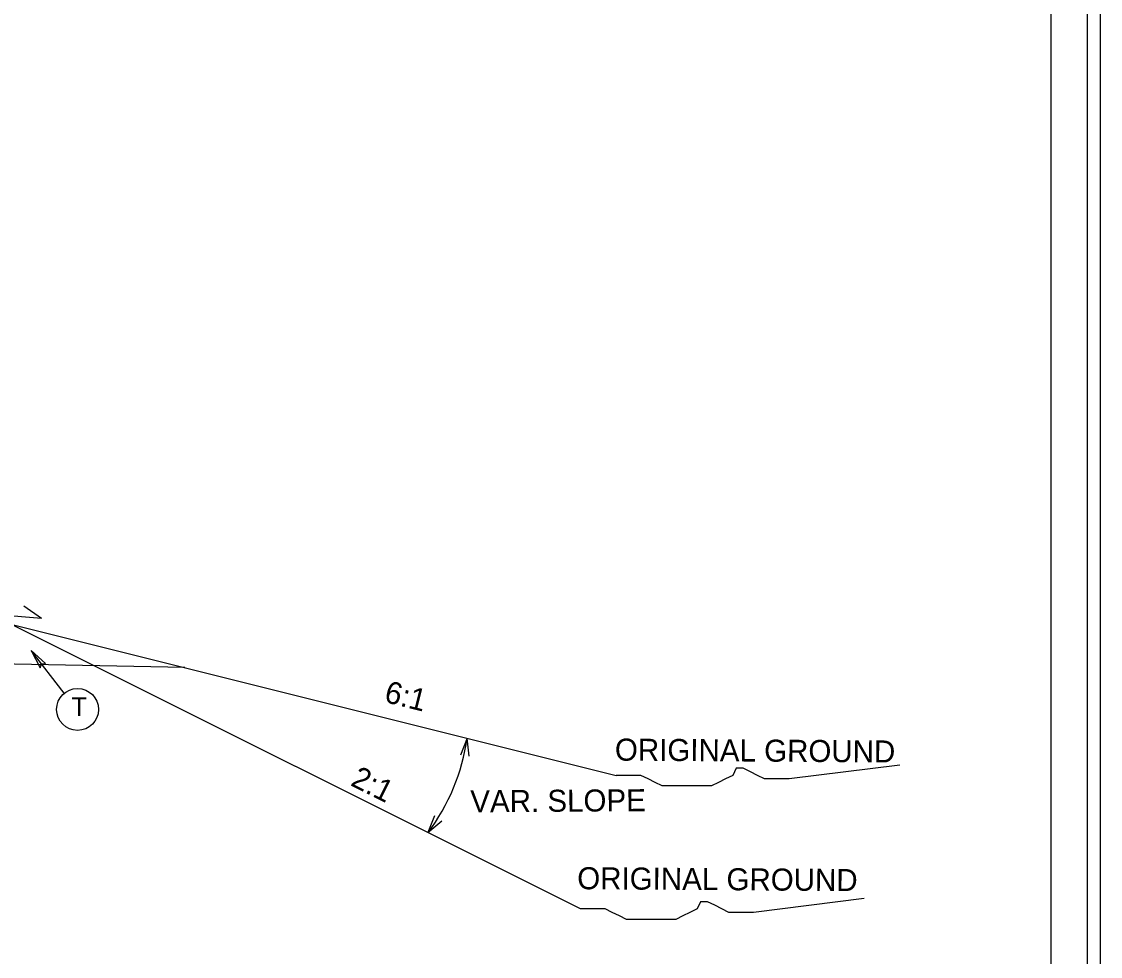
# Model space of a CAD drawing. Extents: x 2111095 to 2115970, y 670428 to 672393.
# Drawn here: x 2112895.7 to 2113267.5, y 671662.9 to 671985.2 of the extents above; entities that cross this region are included whole.
import ezdxf

# ---------------------------------------------------------------- set-up
doc = ezdxf.new("R2010")
doc.units = 0
for name, color, linetype in [('Old_Level_1', 7, 'Continuous'), ('Old_Level_11', 7, 'Continuous'), ('Old_Level_20', 7, 'Continuous'), ('Sheet Plot Border Inside CELL', 7, 'Continuous'), ('Sheet Plot Border Outside CELL', 7, 'Continuous'), ('Sheet Typical CELL', 7, 'Continuous'), ('Typical Pavement Slope CELL', 7, 'Continuous'), ('Typical Pavement Slope Information CELL', 7, 'Continuous')]:
    doc.layers.add(name, color=color, linetype=linetype)

msp = doc.modelspace()

# ---------------------------------------------------------------- linework, layer by layer
at = {"layer": 'Old_Level_1'}
for p, q in [((2112891.98, 671777.43), (2113100.62, 671725.29)), ((2113088.33, 671679.28), (2112891.98, 671777.43))]:
    msp.add_line(p, q, dxfattribs=at)
for points in [[(2113198.38, 671728.84), (2113160.25, 671724.08), (2113157.82, 671724.08), (2113154.16, 671724.08), (2113151.73, 671724.08), (2113149.3, 671725.3), (2113146.86, 671726.52), (2113144.43, 671727.74), (2113142, 671727.74), (2113140.78, 671725.3), (2113138.34, 671724.08), (2113135.91, 671722.86), (2113133.48, 671721.65), (2113131.04, 671721.65), (2113128.61, 671721.65), (2113126.18, 671721.65), (2113123.74, 671721.65), (2113121.31, 671721.65), (2113118.88, 671721.65), (2113116.44, 671721.65), (2113114.01, 671722.86), (2113111.58, 671724.08), (2113109.14, 671725.29), (2113105.49, 671725.29), (2113103.06, 671725.29), (2113100.62, 671725.29)], [(2113186.08, 671682.82), (2113147.96, 671678.07), (2113145.52, 671678.07), (2113141.87, 671678.07), (2113139.44, 671678.07), (2113137, 671679.28), (2113134.57, 671680.5), (2113132.14, 671681.72), (2113129.7, 671681.72), (2113128.48, 671679.28), (2113126.05, 671678.07), (2113123.62, 671676.85), (2113121.18, 671675.63), (2113118.75, 671675.63), (2113116.32, 671675.63), (2113113.88, 671675.63), (2113111.45, 671675.63), (2113109.02, 671675.63), (2113106.58, 671675.63), (2113104.15, 671675.63), (2113101.72, 671676.84), (2113099.28, 671678.07), (2113096.85, 671679.28), (2113093.19, 671679.28), (2113090.76, 671679.28), (2113088.33, 671679.28)]]:
    msp.add_lwpolyline(points, dxfattribs=at)
at = {"layer": 'Old_Level_11'}
msp.add_line((2112910.39, 671753.63), (2112898.92, 671768.39), dxfattribs=at)
msp.add_lwpolyline([(2112903.93, 671763.82), (2112898.92, 671768.39), (2112902.1, 671762.35), (2112902.52, 671763.76)], close=True, dxfattribs=at)
for points in [[(2113049.96, 671731.91), (2113049.24, 671738.13), (2113046.95, 671732.3)], [(2113038.03, 671711.4), (2113035.71, 671705.58), (2113040.49, 671709.62)]]:
    msp.add_lwpolyline(points, dxfattribs=at)
msp.add_circle((2112914.95, 671748.03), 7.22, dxfattribs=at)
msp.add_arc((2112980.3, 671747.68), 69.59, 322.7686, 352.1105, dxfattribs=at)
at = {"layer": 'Sheet Plot Border Inside CELL'}
msp.add_lwpolyline([(2113263.02, 672193.58), (2111596.52, 672193.58), (2111596.52, 671138.48), (2113263.02, 671138.48)], close=True, dxfattribs=at)
at = {"layer": 'Sheet Plot Border Outside CELL'}
msp.add_lwpolyline([(2113267.52, 672216.03), (2111583.52, 672216.03), (2111583.52, 671116.03), (2113267.52, 671116.03)], close=True, dxfattribs=at)
at = {"layer": 'Sheet Typical CELL'}
msp.add_lwpolyline([(2113250.52, 672191.03), (2111750.52, 672191.03), (2111750.52, 671141.03), (2113250.52, 671141.03)], close=True, dxfattribs=at)
at = {"layer": 'Typical Pavement Slope CELL'}
msp.add_line((2112951.96, 671762.44), (2112877.47, 671763.93), dxfattribs=at)
at = {"layer": 'Typical Pavement Slope Information CELL'}
for q in [(2112896.44, 671783.62), (2112874.1, 671781.78)]:
    msp.add_line((2112902.52, 671779.39), q, dxfattribs=at)

# ---------------------------------------------------------------- texts
at = {"layer": 'Old_Level_1'}
for s, height, rotation, p in [('6:1', 7.607, 345.9691, (2113020.34, 671750.68)), ('ORIGINAL GROUND', 7.6069, 359.6033, (2113100.15, 671730.39)), ('2:1', 7.607, 333.4393, (2113008.69, 671722)), ('VAR. SLOPE', 7.607, 0.3967, (2113050.35, 671712.53)), ('ORIGINAL GROUND', 7.6069, 359.6033, (2113087.17, 671686.05))]:
    msp.add_text(s, height=height, rotation=rotation, dxfattribs=at).set_placement(p)
at = {"layer": 'Old_Level_20'}
msp.add_text('T', height=6.46, dxfattribs=at).set_placement((2112912.86, 671745.72))

doc.saveas('drawing.dxf')
